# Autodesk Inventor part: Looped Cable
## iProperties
Author: Administrator
Shininess: 20.0
PropertySet Name: _Private Model Information
Created: 2001-03
Part Number: Looped Cable
Document SubType Name: Modeling
Designer: Administrator
Control State: 0
Master: False
Checked Out: False
PropertySet Name: Design Tracking Control
Density: 0.0
Volumn: 0.0
Area: 0.0
PropertySet Name: Model Information
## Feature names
1. Sweep1
